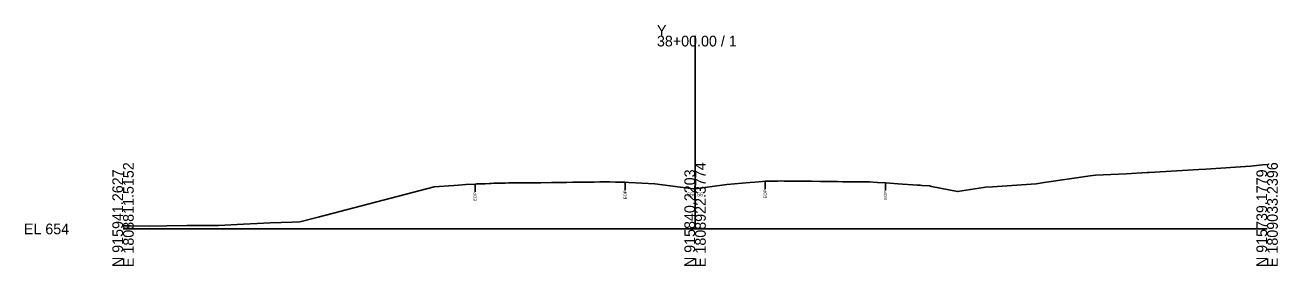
# Model space of a CAD drawing. Extents: x -26 to 3303, y -30 to 9580.
# Drawn here: x 1974.3 to 2302.8, y 7990.3 to 8053.5 of the extents above; entities that cross this region are included whole.
import ezdxf

# ---------------------------------------------------------------- set-up
doc = ezdxf.new("R2010")
doc.units = 0
for name, color, linetype in [('Exist Cross Section Cell', 7, 'Continuous'), ('Exist XS Center Line Elevation Label', 7, 'Continuous'), ('Exist XS Ground Line', 7, 'Continuous'), ('Old_Level_10', 7, 'Continuous')]:
    doc.layers.add(name, color=color, linetype=linetype)

msp = doc.modelspace()

# ---------------------------------------------------------------- linework, layer by layer
at = {"layer": 'Exist Cross Section Cell'}
for p, q in [((2150, 8000), (2150, 8050.65)), ((2000, 8000), (2150, 8000)), ((2150, 8000), (2300, 8000))]:
    msp.add_line(p, q, dxfattribs=at)
at = {"layer": 'Exist XS Ground Line'}
msp.add_lwpolyline([(2000, 8000.82), (2001.87, 8000.79), (2006.9, 8000.71), (2011.48, 8000.84), (2016.72, 8000.94), (2025.01, 8000.92), (2031.57, 8001.22), (2035.21, 8001.45), (2038.54, 8001.62), (2044.38, 8001.8), (2046.36, 8001.88), (2051.2, 8003.11), (2081.55, 8011.02), (2086.73, 8011.42), (2087.94, 8011.5), (2089.92, 8011.63), (2092.3, 8011.78), (2092.78, 8011.79), (2093.78, 8011.81), (2094.94, 8011.83), (2095.98, 8011.9), (2096.52, 8011.94), (2097.27, 8011.99), (2097.69, 8011.99), (2099.37, 8012.02), (2100.24, 8012.03), (2101.2, 8012.05), (2102.01, 8012.06), (2102.75, 8012.07), (2104.16, 8012.06), (2106.14, 8012.09), (2107.33, 8012.1), (2108.63, 8012.12), (2109.52, 8012.13), (2112.33, 8012.15), (2112.9, 8012.16), (2115.26, 8012.19), (2115.78, 8012.2), (2116.27, 8012.21), (2117.94, 8012.24), (2119.77, 8012.26), (2121.48, 8012.29), (2123.51, 8012.3), (2125.02, 8012.32), (2126.42, 8012.33), (2127.11, 8012.34), (2127.67, 8012.35), (2129.16, 8012.3), (2129.82, 8012.26), (2130.58, 8012.26), (2131.65, 8012.25), (2132.64, 8012.21), (2139.41, 8011.82), (2145.47, 8011.04), (2149.55, 8010.49), (2150, 8010.55), (2155.11, 8011.26), (2158.33, 8011.68), (2164.37, 8012.16), (2165.69, 8012.28), (2167.69, 8012.44), (2168.38, 8012.49), (2169.66, 8012.5), (2170.4, 8012.51), (2171.7, 8012.55), (2172.42, 8012.59), (2173.36, 8012.57), (2173.8, 8012.56), (2175.43, 8012.55), (2177.16, 8012.54), (2178.1, 8012.53), (2179.14, 8012.52), (2179.89, 8012.52), (2180.57, 8012.51), (2182.85, 8012.48), (2184.2, 8012.45), (2186.55, 8012.41), (2187.31, 8012.4), (2188.74, 8012.39), (2190.67, 8012.38), (2194.06, 8012.33), (2195.73, 8012.34), (2196.69, 8012.27), (2197.82, 8012.2), (2199.89, 8012.09), (2204.35, 8011.78), (2207.1, 8011.59), (2208.32, 8011.5), (2209.01, 8011.46), (2209.45, 8011.42), (2211.45, 8011.3), (2212, 8011.17), (2218.77, 8009.78), (2225.66, 8010.9), (2226.18, 8010.98), (2227.97, 8011.04), (2239.4, 8011.86), (2241.5, 8012.21), (2254.24, 8014.02), (2255.03, 8014.08), (2263.07, 8014.49), (2268.56, 8014.77), (2269.09, 8014.8), (2282.09, 8015.56), (2283.93, 8015.68), (2295.62, 8016.47), (2298.78, 8016.78), (2300, 8016.88)], dxfattribs=at)
at = {"layer": 'Old_Level_10'}
for p, q in [((2092.3, 8011.78), (2092.3, 8009.73)), ((2131.65, 8012.25), (2131.65, 8010.2)), ((2168.38, 8012.49), (2168.38, 8010.44)), ((2199.89, 8012.09), (2199.89, 8010.04))]:
    msp.add_line(p, q, dxfattribs=at)

# ---------------------------------------------------------------- texts
at = {"layer": 'Exist Cross Section Cell'}
for s, p in [('Y', (2140, 8050.65)), ('38+00.00 / 1', (2140, 8047.85)), ('EL 654', (1974, 7998.6))]:
    msp.add_text(s, height=2.8, dxfattribs=at).set_placement(p)
for s, p in [('E 1808811.5152', (2002.8, 7990)), ('E 1808922.3774', (2152.8, 7990)), ('E 1809033.2396', (2302.8, 7990)), ('N 915941.2627', (2000, 7990)), ('N 915840.2203', (2150, 7990)), ('N 915739.1779', (2300, 7990))]:
    msp.add_text(s, height=2.8, rotation=90, dxfattribs=at).set_placement(p)
at = {"layer": 'Exist XS Center Line Elevation Label'}
msp.add_text('664.55', height=1, dxfattribs=at).set_placement((2147.87, 8008.55))
at = {"layer": 'Old_Level_10'}
for p in [(2132.04, 8007.8), (2168.77, 8008.05), (2200.29, 8007.64), (2092.69, 8007.33)]:
    msp.add_text('EOP', height=0.787, rotation=90, dxfattribs=at).set_placement(p)

doc.saveas('drawing.dxf')
